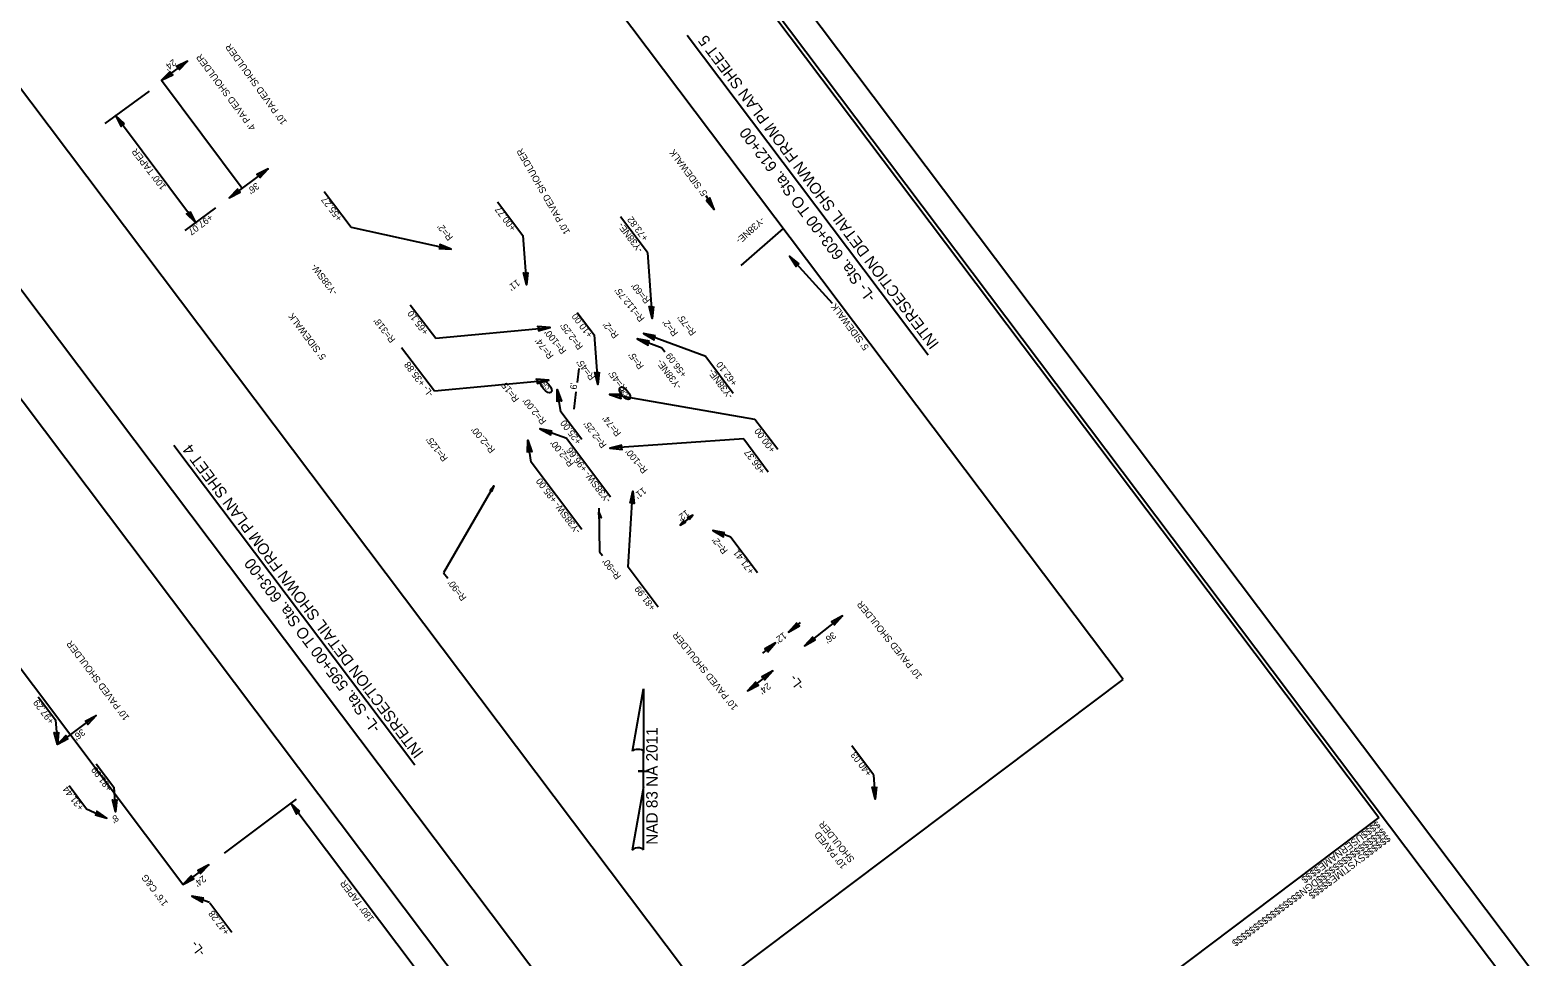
# Model space of a CAD drawing. Extents: x 1262917 to 1264804, y 775326 to 777329.
# Drawn here: x 1263684 to 1264804, y 776000 to 776689 of the extents above; entities that cross this region are included whole.
import ezdxf

# ---------------------------------------------------------------- set-up
doc = ezdxf.new("R2010")
doc.units = 0
for name, color, linetype in [('Old_Level_1', 7, 'Continuous'), ('Prop Dimension', 7, 'Continuous'), ('Prop Dimension Text', 7, 'Continuous'), ('Prop Horizontal Alignment Curve and Spiral Data', 7, 'Continuous'), ('Prop Horizontal Alignment Direction Label', 7, 'Continuous'), ('Prop Lane Lines', 7, 'Continuous'), ('Prop Terminator CELL', 7, 'Continuous'), ('Prop WCC CELL', 7, 'Continuous'), ('Scratch_Level_1', 7, 'Continuous'), ('Sheet Block System Information CELL', 7, 'Continuous'), ('Sheet Plot Border Inside CELL', 7, 'Continuous'), ('Sheet Plot Border Outside CELL', 7, 'Continuous'), ('Sheet Typical CELL', 7, 'Continuous')]:
    doc.layers.add(name, color=color, linetype=linetype)

msp = doc.modelspace()

# ---------------------------------------------------------------- linework, layer by layer
at = {"layer": 'Old_Level_1'}
for p, q in [((1264131.7, 776153.2), (1264139.9, 776199.5)), ((1264139.9, 776199.5), (1264139.9, 776199.5)), ((1264139.9, 776199.5), (1264139.9, 776199.5)), ((1264139.9, 776199.5), (1264139.9, 776151.7)), ((1264139.9, 776126.9), (1264139.9, 776153.1)), ((1264139.9, 776151.7), (1264139.9, 776153.1)), ((1264139.5, 776138.5), (1264135.9, 776138.5)), ((1264135.9, 776138.5), (1264135.9, 776138.5)), ((1264136, 776138.5), (1264144, 776138.5)), ((1264139.9, 776126.9), (1264131.6, 776079.7)), ((1264140, 776079.9), (1264139.9, 776126.9))]:
    msp.add_line(p, q, dxfattribs=at)
for centre, start_param, end_param in [((1264135.8, 776152.7), 0.216388, 2.908219), ((1264135.8, 776079.5), 0.201328, 3.141593)]:
    msp.add_ellipse(centre, major_axis=(4.23, -0.03), ratio=0.461098, start_param=start_param, end_param=end_param, dxfattribs=at)
at = {"layer": 'Prop Dimension'}
for p, q in [((1264028.7, 776350.5), (1263991.3, 776285.9)), ((1264106.7, 776333.8), (1264107.2, 776301.3)), ((1263882, 776117.7), (1263828.6, 776077.4)), ((1263986.3, 775970.9), (1263878, 776114.7))]:
    msp.add_line(p, q, dxfattribs=at)
at = {"layer": 'Prop Dimension Text'}
for p, q in [((1263801.4, 776666), (1263782.1, 776651.7)), ((1263772.8, 776643.7), (1263739.9, 776619.7)), ((1263807.2, 776546.1), (1263747.9, 776625.6)), ((1263861.2, 776585.9), (1263832.3, 776564.3)), ((1263902.9, 776569.1), (1263922.9, 776542.6)), ((1263822.2, 776557), (1263799.2, 776540.2)), ((1264031.5, 776561.5), (1264050.4, 776536.5)), ((1264186.2, 776566), (1264192.5, 776555.7)), ((1264142.9, 776523.8), (1264122.9, 776550.3)), ((1263922.9, 776542.6), (1263997.1, 776526.2)), ((1264050.4, 776536.5), (1264053, 776499.8)), ((1264142.9, 776523.8), (1264146.4, 776474.7)), ((1264280.3, 776485.8), (1264248.4, 776521)), ((1263966.7, 776485), (1263985.6, 776460)), ((1264090.6, 776479.3), (1264103.3, 776462.5)), ((1263985.6, 776460), (1264070.5, 776468)), ((1264103.3, 776462.5), (1264106, 776425.8)), ((1264153.8, 776452.8), (1264135.3, 776459.5)), ((1264186.1, 776446.6), (1264139.8, 776463.5)), ((1263960.1, 776453.3), (1263984.6, 776420.9)), ((1264153.8, 776452.8), (1264155.8, 776450)), ((1264186.1, 776446.6), (1264206.6, 776419.2)), ((1264092, 776437.5), (1264090.7, 776427.3)), ((1263984.6, 776420.9), (1264069.4, 776428.9)), ((1264078.5, 776405.5), (1264075.9, 776421.9)), ((1264088.4, 776407.4), (1264090, 776420.2)), ((1264222.6, 776399.8), (1264114.7, 776418.4)), ((1264094.1, 776384.9), (1264078.5, 776405.5)), ((1264239.7, 776377.3), (1264222.6, 776399.8)), ((1264082.9, 776385.5), (1264063, 776392.8)), ((1264056.6, 776368), (1264054, 776384.4)), ((1264082.9, 776385.5), (1264115.4, 776342.3)), ((1264214.3, 776385.3), (1264114.9, 776378.5)), ((1264214.3, 776385.3), (1264232.6, 776360.9)), ((1264094.2, 776318.1), (1264056.6, 776368)), ((1264128.5, 776289.9), (1264132, 776346.5)), ((1264176.6, 776328.7), (1264167.2, 776321.3)), ((1264204.7, 776312.4), (1264191.5, 776317.2)), ((1264204.7, 776312.3), (1264224.6, 776286)), ((1264107.2, 776301.3), (1264109.4, 776298.6)), ((1264150.7, 776260.4), (1264128.5, 776289.9)), ((1263991.3, 776285.9), (1263994.6, 776281.9)), ((1264247.7, 776241.8), (1264256.4, 776249)), ((1264287.7, 776253.8), (1264259.5, 776231.5)), ((1264228.6, 776226.2), (1264237.9, 776233.8)), ((1264235.9, 776212.9), (1264217.1, 776198.1)), ((1263690.3, 776193.7), (1263703.4, 776176.5)), ((1263703.4, 776176.5), (1263704.7, 776158.2)), ((1263704.7, 776158.2), (1263733.4, 776179.9)), ((1264310.7, 776135.8), (1264294.6, 776157.3)), ((1263733.6, 776143.9), (1263746.6, 776126.6)), ((1264310.7, 776135.8), (1264312, 776117.6)), ((1263713.4, 776127.8), (1263726.4, 776110.5)), ((1263746.6, 776126.6), (1263747.9, 776108.3)), ((1263726.4, 776110.5), (1263741.5, 776103.5)), ((1263817.1, 776068.8), (1263797.9, 776054.3)), ((1263817.7, 776040.8), (1263804.5, 776045.6)), ((1263817.8, 776040.7), (1263834.3, 776018.8))]:
    msp.add_line(p, q, dxfattribs=at)
for points in [[(1263754.6, 776619.3), (1263747.9, 776625.6), (1263752.1, 776617.4), (1263752.7, 776619.3)], [(1263803.1, 776554.2), (1263807.2, 776546.1), (1263800.6, 776552.4), (1263802.5, 776552.4)], [(1263884.7, 776108.4), (1263878, 776114.7), (1263882.2, 776106.5), (1263882.8, 776108.4)]]:
    msp.add_lwpolyline(points, close=True, dxfattribs=at)
at = {"layer": 'Prop Horizontal Alignment Curve and Spiral Data'}
for p, q in [((1264351.2, 776447.5), (1264172.3, 776685)), ((1263970, 776143), (1263791.1, 776380.5))]:
    msp.add_line(p, q, dxfattribs=at)
at = {"layer": 'Prop Lane Lines'}
for p, q in [((1263782.1, 776651.7), (1263841.9, 776571.5)), ((1263797.9, 776054.3), (1263565, 776363.6))]:
    msp.add_line(p, q, dxfattribs=at)
msp.add_lwpolyline([(1264212.4, 776514), (1264243.8, 776541.6)], dxfattribs=at)
at = {"layer": 'Prop Terminator CELL'}
for points in [[(1263788.4, 776658.3), (1263782.1, 776651.7), (1263790.3, 776655.8), (1263788.5, 776656.4)], [(1263795.1, 776659.4), (1263801.4, 776666), (1263793.1, 776661.9), (1263795, 776661.3)], [(1263854.9, 776579.3), (1263861.2, 776585.9), (1263852.9, 776581.7), (1263854.8, 776581.2)], [(1263838.6, 776571), (1263832.3, 776564.3), (1263840.5, 776568.5), (1263838.6, 776569.1)], [(1264186.4, 776562.6), (1264192.5, 776555.7), (1264189.1, 776564.3), (1264188.3, 776562.4)], [(1263988, 776526.7), (1263997.1, 776526.2), (1263988.7, 776529.7), (1263989.4, 776527.9)], [(1264255.6, 776515.4), (1264248.4, 776521), (1264253.3, 776513.3), (1264253.7, 776515.2)], [(1264053.9, 776508.9), (1264053, 776499.8), (1264050.8, 776508.7), (1264052.5, 776507.7)], [(1264147.3, 776483.7), (1264146.4, 776474.7), (1264144.2, 776483.6), (1264145.9, 776482.5)], [(1264061.7, 776465.5), (1264070.5, 776468), (1264061.3, 776468.7), (1264062.6, 776467.2)], [(1264144.3, 776457.9), (1264135.3, 776459.5), (1264143.3, 776454.9), (1264142.7, 776456.8)], [(1264148.8, 776461.9), (1264139.8, 776463.5), (1264147.8, 776458.9), (1264147.2, 776460.8)], [(1264106.9, 776434.9), (1264106, 776425.8), (1264103.7, 776434.7), (1264105.4, 776433.6)], [(1264060.7, 776426.5), (1264069.5, 776429), (1264060.3, 776429.7), (1264061.6, 776428.2)], [(1264075.8, 776412.8), (1264075.9, 776421.9), (1264078.9, 776413.2), (1264077.1, 776414.1)], [(1264123.8, 776418.3), (1264114.7, 776418.3), (1264123.3, 776415.2), (1264122.5, 776417)], [(1264072, 776391.1), (1264063, 776392.8), (1264071, 776388.2), (1264070.4, 776390.1)], [(1264053.8, 776375.3), (1264054, 776384.4), (1264057, 776375.7), (1264055.2, 776376.6)], [(1264123.8, 776380.6), (1264114.9, 776378.5), (1264124, 776377.5), (1264122.8, 776379)], [(1264025.8, 776347), (1264028.7, 776350.5), (1264027.1, 776346.2), (1264026.7, 776347.1)], [(1264129.9, 776337.6), (1264132, 776346.5), (1264133.1, 776337.3), (1264131.6, 776338.6)], [(1264107, 776326.3), (1264106.8, 776330.9), (1264108.5, 776326.6), (1264107.6, 776327)], [(1264170.2, 776324.6), (1264167.2, 776321.3), (1264171.2, 776323.4), (1264170.2, 776323.7)], [(1264173.7, 776325.4), (1264176.6, 776328.7), (1264172.7, 776326.6), (1264173.6, 776326.3)], [(1264200.4, 776315.6), (1264191.5, 776317.2), (1264199.4, 776312.6), (1264198.9, 776314.5)], [(1264253.7, 776248.7), (1264247.7, 776241.8), (1264255.7, 776246.3), (1264253.8, 776246.8)], [(1264281.6, 776247), (1264287.7, 776253.8), (1264279.6, 776249.5), (1264281.5, 776248.9)], [(1264231.9, 776226.9), (1264237.9, 776233.8), (1264229.9, 776229.3), (1264231.8, 776228.8)], [(1264265.6, 776238.3), (1264259.5, 776231.5), (1264267.5, 776235.9), (1264265.7, 776236.4)], [(1264229.8, 776206.1), (1264235.9, 776212.9), (1264227.8, 776208.6), (1264229.7, 776208)], [(1264223.2, 776204.8), (1264217.1, 776198.1), (1264225.2, 776202.4), (1264223.3, 776202.9)], [(1263725.3, 776175.7), (1263733.4, 776179.9), (1263727.2, 776173.1), (1263727.1, 776175.1)], [(1263705.6, 776167.3), (1263704.7, 776158.2), (1263702.4, 776167.1), (1263704.1, 776166.1)], [(1263712.8, 776162.4), (1263704.7, 776158.2), (1263710.9, 776164.9), (1263711, 776163)], [(1264312.9, 776126.7), (1264312, 776117.6), (1264309.8, 776126.5), (1264311.5, 776125.4)], [(1263732.7, 776105.9), (1263741.5, 776103.5), (1263733.9, 776108.7), (1263734.3, 776106.8)], [(1263748.8, 776117.4), (1263747.9, 776108.3), (1263745.6, 776117.2), (1263747.3, 776116.2)], [(1263810.8, 776062.1), (1263817.1, 776068.8), (1263808.9, 776064.6), (1263810.8, 776064)], [(1263804.2, 776061), (1263797.9, 776054.3), (1263806.1, 776058.5), (1263804.2, 776059.1)], [(1263813.5, 776044), (1263804.5, 776045.6), (1263812.4, 776041), (1263811.9, 776042.9)]]:
    msp.add_lwpolyline(points, close=True, dxfattribs=at)
at = {"layer": 'Prop WCC CELL'}
for centre in [(1264067.7, 776424.1), (1264126, 776419.2)]:
    msp.add_ellipse(centre, major_axis=(-3.52, 4.36), ratio=0.462467, dxfattribs=at)
at = {"layer": 'Scratch_Level_1'}
msp.add_lwpolyline([(1263815.7, 775698.6), (1263313.4, 776365.4), (1263569.5, 776558.3), (1264071.7, 775891.5)], close=True, dxfattribs=at)
at = {"layer": 'Sheet Block System Information CELL'}
msp.add_line((1264685.9, 776104), (1264685.9, 776104), dxfattribs=at)
at = {"layer": 'Sheet Plot Border Inside CELL'}
msp.add_lwpolyline([(1264780.2, 775982.9), (1263777.9, 777313.6), (1262935.2, 776678.9), (1263937.5, 775348.2)], close=True, dxfattribs=at)
at = {"layer": 'Sheet Plot Border Outside CELL'}
msp.add_lwpolyline([(1262916.5, 776670.5), (1263929.4, 775325.7), (1264804, 775984.5), (1263791.2, 777329.3)], close=True, dxfattribs=at)
at = {"layer": 'Sheet Typical CELL'}
for p, q in [((1263783.4, 777302.1), (1264685.9, 776104)), ((1264685.9, 776104), (1263847.2, 775472.3))]:
    msp.add_line(p, q, dxfattribs=at)
for points in [[(1264496.1, 776206.6), (1263954.6, 776925.5), (1263643.1, 776690.8), (1264184.6, 775972)], [(1263313.4, 776365.4), (1263815.7, 775698.6), (1264110.7, 775920.9), (1263608.5, 776587.6)]]:
    msp.add_lwpolyline(points, close=True, dxfattribs=at)

# ---------------------------------------------------------------- texts
at = {"layer": 'Old_Level_1'}
msp.add_text('NAD 83 NA 2011', height=8.5, rotation=90, dxfattribs=at).set_placement((1264150.4, 776083.8))
at = {"layer": 'Prop Dimension'}
for s, rotation, p in [("4' PAVED SHOULDER", 126.6628, (1263852.2, 776616.7)), ("10' PAVED SHOULDER", 125.876, (1263875.4, 776620.8)), ("100' TAPER", 127.7494, (1263785.8, 776572.7)), ("10' PAVED SHOULDER", 119.8312, (1264085.6, 776538.9)), ('+55.27', 126.9874, (1263916.6, 776549.3)), ('+00.77', 126.9874, (1264045.6, 776542)), ('-Y38NE- ', 126.9874, (1264139.8, 776526)), ('+73.82', 126.9874, (1264143.8, 776534.6)), ("R=2'", 128.9157, (1263998.8, 776535.1)), ("R=60'", 128.9157, (1264145.2, 776488.3)), ('+65.10', 126.9874, (1263980.6, 776464.8)), ('+10.00', 126.9874, (1264102.6, 776462.7)), ("R=318'", 127.7494, (1263956, 776459.1)), ("R=2.25'", 127.0895, (1264095.4, 776453.9)), ("R=75'", 127.7494, (1264179.3, 776464.4)), ("R=74'", 127.5609, (1264073.5, 776447.1)), ("R=100'", 128.9157, (1264083, 776450.8)), ('+56.09', 126.9874, (1264172.4, 776433.3)), ('-L- +35.88', 126.9874, (1263984.2, 776418.8)), ("R=45'", 127.9329, (1264104.4, 776431.3)), ("R=45'", 127.9329, (1264128.1, 776422.9)), ('-Y38NE- ', 126.9874, (1264168.5, 776424.5)), ('-Y38NE- ', 126.9874, (1264206.7, 776417.4)), ('+62.10', 126.9874, (1264209.9, 776426.9)), ("R=15'", 127.7494, (1264047.9, 776415)), ("6'", 87.0077, (1264090.4, 776421.9)), ("R=2.00'", 128.9157, (1264068.1, 776398.5)), ("R=74'", 127.7494, (1264123.6, 776389.5)), ("R=2.00'", 130.0821, (1264030.1, 776377.3)), ('+25.00', 126.9874, (1264094.1, 776383.4)), ("R=2.25'", 126.817, (1264112.8, 776380.8)), ('+00.00', 126.9874, (1264238.2, 776377.4)), ("R=125'", 127.7494, (1263994.9, 776370.9)), ("R=2.00'", 128.9157, (1264088.6, 776367.1)), ('-Y38SW- +96.66', 126.9874, (1264116, 776340)), ("R=100'", 128.9157, (1264143.3, 776362.1)), ('+66.37', 126.9874, (1264230.7, 776361.5)), ('-Y38SW- +85.00', 126.9874, (1264093.5, 776317.1)), ("R=2'", 128.9157, (1264202.8, 776302.3)), ('+71.41', 126.9874, (1264222.5, 776287.1)), ("R=90'", 127.7494, (1264123.6, 776283.3)), ("R=90'", 127.7494, (1264008.8, 776267.4)), ("10' PAVED SHOULDER", 126.9874, (1263758.4, 776178.3)), ('+97.29', 126.9874, (1263702.7, 776175.7)), ('+40.03', 126.9874, (1264309.8, 776136.9)), ('+81.99', 126.9874, (1263745.8, 776125.8)), ('+31.44', 126.9874, (1263724.7, 776111.4)), ('1\'6" C&G', 126.9874, (1263787.1, 776040.5)), ('+47.28', 126.9874, (1263832.8, 776019))]:
    msp.add_text(s, height=5, rotation=rotation, dxfattribs=at).set_placement(p)
at = {"layer": 'Prop Dimension Text'}
for s, rotation, p in [("24'", 216.9874, (1263790.7, 776667.7)), ("5' SIDEWALK", 126.9874, (1264187.6, 776567.9)), ("36'", 216.9874, (1263852.3, 776576)), ('+97.07', 216.8584, (1263817.8, 776552.6)), ('-Y38NE- ', 222.05, (1264227.2, 776550.6)), ('-Y38SW-', 127.5158, (1263913, 776494.5)), ("11'", 216.9874, (1264045.9, 776504.1)), ("R=112.75'", 128.9157, (1264141, 776474.8)), ("5' SIDEWALK", 126.9874, (1263904.5, 776446.3)), ("5' SIDEWALK", 126.9874, (1264307.6, 776453.4)), ("R=2'", 128.9157, (1264121.8, 776462.4)), ("R=2'", 128.1676, (1264165.9, 776464)), ("R=5'", 126.9874, (1264140.5, 776439.4)), ("11'", 216.9874, (1264139.7, 776349.6)), ("12'", 216.9874, (1264171.6, 776332.9)), ('+81.99', 126.7391, (1264149.2, 776260.1)), ("10' PAVED SHOULDER", 128.9157, (1264347.2, 776209.2)), ("10' PAVED SHOULDER", 128.9157, (1264210.3, 776186.2)), ("12'", 216.9874, (1264243.9, 776242)), ("36'", 216.9874, (1264280.6, 776242.2)), ("24'", 216.9874, (1264232.1, 776204.4)), ("36'", 216.9874, (1263723, 776170.2)), ("8'", 216.9874, (1263747.9, 776106.4)), ('SHOULDER', 128.9157, (1264296.9, 776073)), ("10' PAVED", 128.9157, (1264291.1, 776068.3)), ("24'", 216.9874, (1263812.8, 776061.3)), ("180' TAPER", 126.9874, (1263940.2, 776028.8))]:
    msp.add_text(s, height=5, rotation=rotation, dxfattribs=at).set_placement(p)
at = {"layer": 'Prop Horizontal Alignment Curve and Spiral Data'}
for s, p in [('INTERSECTION DETAIL SHOWN FROM PLAN SHEET 5', (1264359.8, 776456)), ('-L- Sta. 603+00 TO Sta. 612+00', (1264312.8, 776490.6)), ('INTERSECTION DETAIL SHOWN FROM PLAN SHEET 4', (1263977, 776152.1)), ('-L- Sta. 595+00 TO Sta. 603+00', (1263945.1, 776170.6))]:
    msp.add_text(s, height=8.32, rotation=126.9874, dxfattribs=at).set_placement(p)
at = {"layer": 'Prop Horizontal Alignment Direction Label'}
for p in [(1264259.6, 776201.6), (1263814.9, 776004)]:
    msp.add_text('-L-', height=7, rotation=126.9852, dxfattribs=at).set_placement(p)
at = {"layer": 'Prop WCC CELL'}
for p in [(1264070.4, 776423.2), (1264128.7, 776418.3)]:
    msp.add_text('CR', height=3, rotation=128.9157, dxfattribs=at).set_placement(p)
at = {"layer": 'Sheet Block System Information CELL'}
for s, p in [('$$$$USERNAME$$$$', (1264684.6, 776101.7)), ('$$$$$$$$$$$$$$$$DGN$$$$$$$$$$$$$$$$', (1264688.6, 776096.5)), ('$$$$$$SYSTIME$$$$$', (1264692.2, 776091.6))]:
    msp.add_text(s, height=5.25, rotation=216.9874, dxfattribs=at).set_placement(p)

doc.saveas('drawing.dxf')
